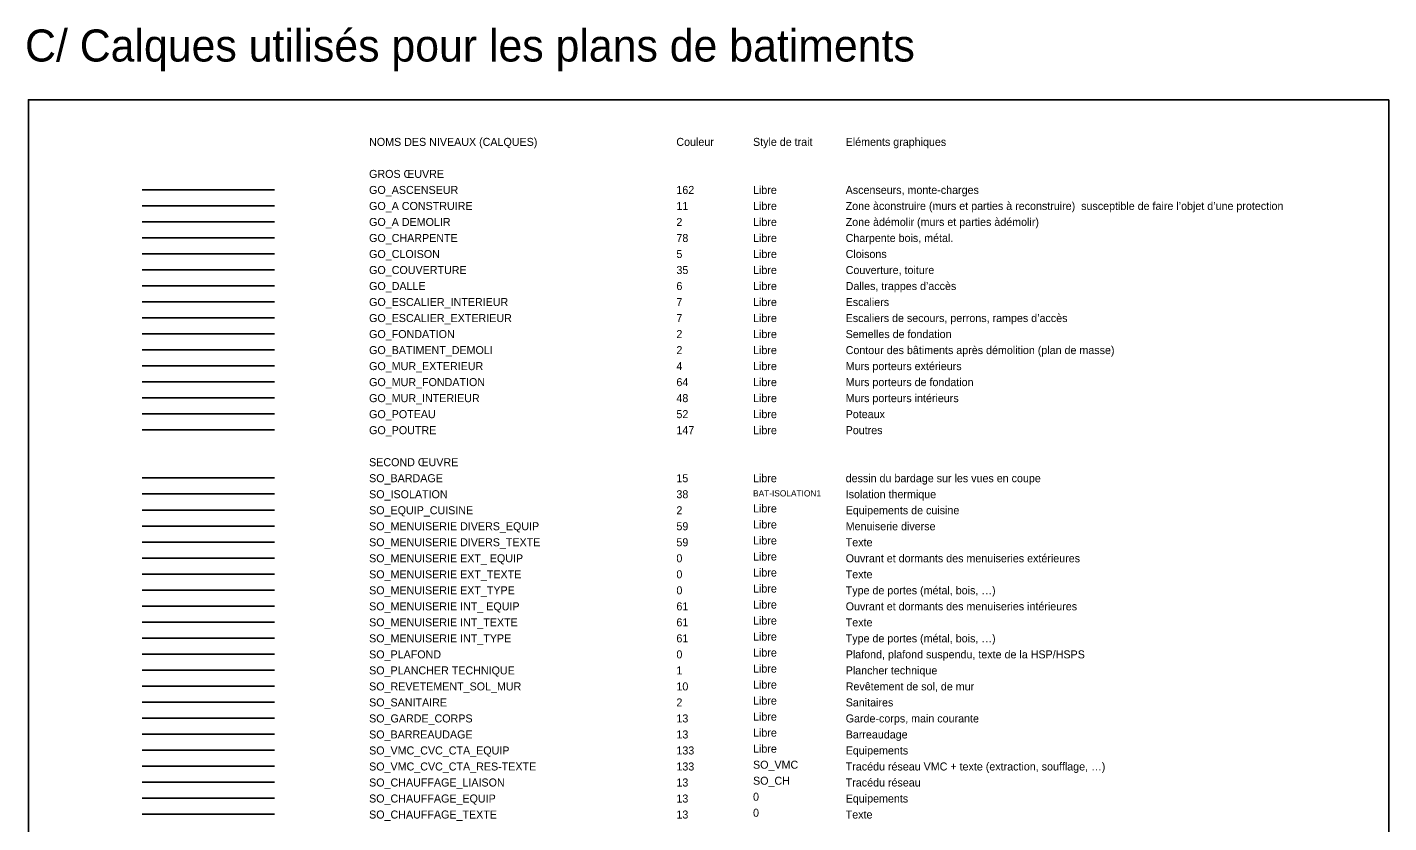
# Model space of a CAD drawing. Extents: x -60 to 214, y -380 to -21.
# Drawn here: x 123.6 to 208.7, y -70.9 to -21.2 of the extents above; entities that cross this region are included whole.
import ezdxf

# ---------------------------------------------------------------- set-up
doc = ezdxf.new("R2010")
doc.units = 0
for name, color, linetype in [('Default', 7, 'Continuous'), ('DH_TEXTE', 7, 'Continuous'), ('GO_A CONSTRUIRE', 7, 'Continuous'), ('GO_A DEMOLIR', 7, 'Continuous'), ('GO_ASCENSEUR', 7, 'Continuous'), ('GO_BATIMENT_DEMOLI', 7, 'Continuous'), ('GO_CHARPENTE', 7, 'Continuous'), ('GO_CLOISON', 7, 'Continuous'), ('GO_COUVERTURE', 7, 'Continuous'), ('GO_DALLE', 7, 'Continuous'), ('GO_ESCALIER_EXTERIEUR', 7, 'Continuous'), ('GO_ESCALIER_INTERIEUR', 7, 'Continuous'), ('GO_FONDATION', 7, 'Continuous'), ('GO_MUR_EXTERIEUR', 7, 'Continuous'), ('GO_MUR_FONDATION', 7, 'Continuous'), ('GO_MUR_INTERIEUR', 7, 'Continuous'), ('GO_POTEAU', 7, 'Continuous'), ('GO_POUTRE', 7, 'Continuous'), ('SO_BARDAGE', 7, 'Continuous'), ('SO_BARREAUDAGE', 7, 'Continuous'), ('SO_CHAUFFAGE_EQUIP', 7, 'Continuous'), ('SO_CHAUFFAGE_LIAISON', 7, 'Continuous'), ('SO_CHAUFFAGE_TEXTE', 7, 'Continuous'), ('SO_EQUIP_CUISINE', 7, 'Continuous'), ('SO_GARDE_CORPS', 7, 'Continuous'), ('SO_ISOLATION', 7, 'Continuous'), ('SO_MENUISERIE DIVERS_EQUIP', 7, 'Continuous'), ('SO_MENUISERIE DIVERS_TEXTE', 7, 'Continuous'), ('SO_MENUISERIE EXT_ EQUIP', 7, 'Continuous'), ('SO_MENUISERIE EXT_TEXTE', 7, 'Continuous'), ('SO_MENUISERIE EXT_TYPE', 7, 'Continuous'), ('SO_MENUISERIE INT_ EQUIP', 7, 'Continuous'), ('SO_MENUISERIE INT_TEXTE', 7, 'Continuous'), ('SO_MENUISERIE INT_TYPE', 7, 'Continuous'), ('SO_PLAFOND', 7, 'Continuous'), ('SO_PLANCHER TECHNIQUE', 7, 'Continuous'), ('SO_REVETEMENT_SOL_MUR', 7, 'Continuous'), ('SO_SANITAIRE', 7, 'Continuous'), ('SO_VMC_CVC_CTA_EQUIP', 7, 'Continuous'), ('SO_VMC_CVC_CTA_RES-TEXTE', 7, 'Continuous')]:
    doc.layers.add(name, color=color, linetype=linetype)

msp = doc.modelspace()

# ---------------------------------------------------------------- linework, layer by layer
at = {"layer": 'Default'}
msp.add_lwpolyline([(208.701, -25.727), (123.7, -25.727), (123.7, -120.902), (208.701, -120.902)], close=True, dxfattribs=at)
at = {"layer": 'GO_A CONSTRUIRE'}
msp.add_line((139.084, -32.345), (130.805, -32.345), dxfattribs=at)
at = {"layer": 'GO_A DEMOLIR'}
msp.add_line((139.084, -33.345), (130.805, -33.345), dxfattribs=at)
at = {"layer": 'GO_ASCENSEUR'}
msp.add_line((139.084, -31.345), (130.805, -31.345), dxfattribs=at)
at = {"layer": 'GO_BATIMENT_DEMOLI'}
msp.add_line((139.084, -41.345), (130.805, -41.345), dxfattribs=at)
at = {"layer": 'GO_CHARPENTE'}
msp.add_line((139.084, -34.345), (130.805, -34.345), dxfattribs=at)
at = {"layer": 'GO_CLOISON'}
msp.add_line((139.084, -35.345), (130.805, -35.345), dxfattribs=at)
at = {"layer": 'GO_COUVERTURE'}
msp.add_line((139.084, -36.345), (130.805, -36.345), dxfattribs=at)
at = {"layer": 'GO_DALLE'}
msp.add_line((139.084, -37.345), (130.805, -37.345), dxfattribs=at)
at = {"layer": 'GO_ESCALIER_EXTERIEUR'}
msp.add_line((139.084, -39.345), (130.805, -39.345), dxfattribs=at)
at = {"layer": 'GO_ESCALIER_INTERIEUR'}
msp.add_line((139.084, -38.345), (130.805, -38.345), dxfattribs=at)
at = {"layer": 'GO_FONDATION'}
msp.add_line((139.084, -40.345), (130.805, -40.345), dxfattribs=at)
at = {"layer": 'GO_MUR_EXTERIEUR'}
msp.add_line((139.084, -42.345), (130.805, -42.345), dxfattribs=at)
at = {"layer": 'GO_MUR_FONDATION'}
msp.add_line((139.084, -43.345), (130.805, -43.345), dxfattribs=at)
at = {"layer": 'GO_MUR_INTERIEUR'}
msp.add_line((139.084, -44.345), (130.805, -44.345), dxfattribs=at)
at = {"layer": 'GO_POTEAU'}
msp.add_line((139.084, -45.345), (130.805, -45.345), dxfattribs=at)
at = {"layer": 'GO_POUTRE'}
msp.add_line((139.084, -46.345), (130.805, -46.345), dxfattribs=at)
at = {"layer": 'SO_BARDAGE'}
msp.add_line((139.084, -49.345), (130.805, -49.345), dxfattribs=at)
at = {"layer": 'SO_BARREAUDAGE'}
msp.add_line((139.084, -65.345), (130.805, -65.345), dxfattribs=at)
at = {"layer": 'SO_CHAUFFAGE_EQUIP'}
msp.add_line((139.084, -69.345), (130.805, -69.345), dxfattribs=at)
at = {"layer": 'SO_CHAUFFAGE_LIAISON'}
msp.add_line((130.805, -68.345), (139.084, -68.345), dxfattribs=at)
at = {"layer": 'SO_CHAUFFAGE_TEXTE'}
msp.add_line((139.084, -70.345), (130.805, -70.345), dxfattribs=at)
at = {"layer": 'SO_EQUIP_CUISINE'}
msp.add_line((139.084, -51.345), (130.805, -51.345), dxfattribs=at)
at = {"layer": 'SO_GARDE_CORPS'}
msp.add_line((139.084, -64.345), (130.805, -64.345), dxfattribs=at)
at = {"layer": 'SO_ISOLATION'}
msp.add_line((139.084, -50.345), (130.805, -50.345), dxfattribs=at)
at = {"layer": 'SO_MENUISERIE DIVERS_EQUIP'}
msp.add_line((139.084, -52.345), (130.805, -52.345), dxfattribs=at)
at = {"layer": 'SO_MENUISERIE DIVERS_TEXTE'}
msp.add_line((139.084, -53.345), (130.805, -53.345), dxfattribs=at)
at = {"layer": 'SO_MENUISERIE EXT_ EQUIP'}
msp.add_line((139.084, -54.345), (130.805, -54.345), dxfattribs=at)
at = {"layer": 'SO_MENUISERIE EXT_TEXTE'}
msp.add_line((139.084, -55.345), (130.805, -55.345), dxfattribs=at)
at = {"layer": 'SO_MENUISERIE EXT_TYPE'}
msp.add_line((139.084, -56.345), (130.805, -56.345), dxfattribs=at)
at = {"layer": 'SO_MENUISERIE INT_ EQUIP'}
msp.add_line((139.084, -57.345), (130.805, -57.345), dxfattribs=at)
at = {"layer": 'SO_MENUISERIE INT_TEXTE'}
msp.add_line((139.084, -58.345), (130.805, -58.345), dxfattribs=at)
at = {"layer": 'SO_MENUISERIE INT_TYPE'}
msp.add_line((139.084, -59.345), (130.805, -59.345), dxfattribs=at)
at = {"layer": 'SO_PLAFOND'}
msp.add_line((139.084, -60.345), (130.805, -60.345), dxfattribs=at)
at = {"layer": 'SO_PLANCHER TECHNIQUE'}
msp.add_line((139.084, -61.345), (130.805, -61.345), dxfattribs=at)
at = {"layer": 'SO_REVETEMENT_SOL_MUR'}
msp.add_line((139.084, -62.345), (130.805, -62.345), dxfattribs=at)
at = {"layer": 'SO_SANITAIRE'}
msp.add_line((139.084, -63.345), (130.805, -63.345), dxfattribs=at)
at = {"layer": 'SO_VMC_CVC_CTA_EQUIP'}
msp.add_line((139.084, -66.345), (130.805, -66.345), dxfattribs=at)
at = {"layer": 'SO_VMC_CVC_CTA_RES-TEXTE'}
msp.add_line((130.805, -67.345), (139.084, -67.345), dxfattribs=at)

# ---------------------------------------------------------------- texts
at = {"layer": 'Default'}
msp.add_text('C/ Calques utilisés pour les plans de batiments', height=2, dxfattribs=at).set_placement((123.489, -23.342))
at = {"layer": 'DH_TEXTE'}
for s, p in [('Eléments graphiques', (174.765, -28.61)), ('NOMS DES NIVEAUX (CALQUES) ', (144.987, -28.61)), ('Couleur ', (164.186, -28.61)), ('Style de trait ', (168.976, -28.61)), ('GROS ŒUVRE ', (144.987, -30.61)), ('SECOND ŒUVRE ', (144.987, -48.61))]:
    msp.add_text(s, height=0.5, dxfattribs=at).set_placement(p)
at = {"layer": 'GO_A CONSTRUIRE'}
for s, p in [('GO_A CONSTRUIRE  ', (144.987, -32.61)), ('11 ', (164.189, -32.61)), ('Libre ', (168.981, -32.61)), ('Zone àconstruire (murs et parties à reconstruire)  susceptible de faire l’objet d’une protection ', (174.765, -32.61))]:
    msp.add_text(s, height=0.5, dxfattribs=at).set_placement(p)
at = {"layer": 'GO_A DEMOLIR'}
for s, p in [('GO_A DEMOLIR  ', (144.987, -33.61)), ('2 ', (164.189, -33.61)), ('Libre ', (168.981, -33.61)), ('Zone àdémolir (murs et parties àdémolir) ', (174.765, -33.61))]:
    msp.add_text(s, height=0.5, dxfattribs=at).set_placement(p)
at = {"layer": 'GO_ASCENSEUR'}
for s, p in [('GO_ASCENSEUR ', (144.987, -31.61)), ('162 ', (164.186, -31.61)), ('Libre ', (168.976, -31.61)), ('Ascenseurs, monte-charges  ', (174.765, -31.61))]:
    msp.add_text(s, height=0.5, dxfattribs=at).set_placement(p)
at = {"layer": 'GO_BATIMENT_DEMOLI'}
for s, p in [('GO_BATIMENT_DEMOLI ', (144.987, -41.61)), ('2 ', (164.189, -41.61)), ('Libre ', (168.981, -41.61)), ('Contour des bâtiments après démolition (plan de masse) ', (174.765, -41.61))]:
    msp.add_text(s, height=0.5, dxfattribs=at).set_placement(p)
at = {"layer": 'GO_CHARPENTE'}
for s, p in [('GO_CHARPENTE ', (144.987, -34.61)), ('78 ', (164.189, -34.61)), ('Libre ', (168.981, -34.61)), ('Charpente bois, métal. ', (174.765, -34.61))]:
    msp.add_text(s, height=0.5, dxfattribs=at).set_placement(p)
at = {"layer": 'GO_CLOISON'}
for s, p in [('GO_CLOISON ', (144.987, -35.61)), ('5 ', (164.189, -35.61)), ('Libre ', (168.981, -35.61)), ('Cloisons  ', (174.765, -35.61))]:
    msp.add_text(s, height=0.5, dxfattribs=at).set_placement(p)
at = {"layer": 'GO_COUVERTURE'}
for s, p in [('GO_COUVERTURE ', (144.987, -36.61)), ('35 ', (164.189, -36.61)), ('Libre ', (168.981, -36.61)), ('Couverture, toiture ', (174.765, -36.61))]:
    msp.add_text(s, height=0.5, dxfattribs=at).set_placement(p)
at = {"layer": 'GO_DALLE'}
for s, p in [('GO_DALLE ', (144.987, -37.61)), ('6 ', (164.189, -37.61)), ('Libre ', (168.981, -37.61)), ('Dalles, trappes d’accès ', (174.765, -37.61))]:
    msp.add_text(s, height=0.5, dxfattribs=at).set_placement(p)
at = {"layer": 'GO_ESCALIER_EXTERIEUR'}
for s, p in [('GO_ESCALIER_EXTERIEUR ', (144.987, -39.61)), ('7 ', (164.189, -39.61)), ('Libre ', (168.981, -39.61)), ('Escaliers de secours, perrons, rampes d’accès ', (174.765, -39.61))]:
    msp.add_text(s, height=0.5, dxfattribs=at).set_placement(p)
at = {"layer": 'GO_ESCALIER_INTERIEUR'}
for s, p in [('GO_ESCALIER_INTERIEUR ', (144.987, -38.61)), ('7 ', (164.189, -38.61)), ('Libre ', (168.981, -38.61)), ('Escaliers ', (174.765, -38.61))]:
    msp.add_text(s, height=0.5, dxfattribs=at).set_placement(p)
at = {"layer": 'GO_FONDATION'}
for s, p in [('GO_FONDATION ', (144.987, -40.61)), ('2 ', (164.189, -40.61)), ('Libre ', (168.981, -40.61)), ('Semelles de fondation ', (174.765, -40.61))]:
    msp.add_text(s, height=0.5, dxfattribs=at).set_placement(p)
at = {"layer": 'GO_MUR_EXTERIEUR'}
for s, p in [('GO_MUR_EXTERIEUR          ', (144.987, -42.61)), ('4 ', (164.189, -42.61)), ('Libre ', (168.981, -42.61)), ('Murs porteurs extérieurs  ', (174.765, -42.61))]:
    msp.add_text(s, height=0.5, dxfattribs=at).set_placement(p)
at = {"layer": 'GO_MUR_FONDATION'}
for s, p in [('GO_MUR_FONDATION ', (144.987, -43.61)), ('64 ', (164.189, -43.61)), ('Libre ', (168.981, -43.61)), ('Murs porteurs de fondation  ', (174.765, -43.61))]:
    msp.add_text(s, height=0.5, dxfattribs=at).set_placement(p)
at = {"layer": 'GO_MUR_INTERIEUR'}
for s, p in [('GO_MUR_INTERIEUR                ', (144.987, -44.61)), ('48 ', (164.189, -44.61)), ('Libre ', (168.981, -44.61)), ('Murs porteurs intérieurs  ', (174.765, -44.61))]:
    msp.add_text(s, height=0.5, dxfattribs=at).set_placement(p)
at = {"layer": 'GO_POTEAU'}
for s, p in [('Libre ', (168.981, -45.61)), ('GO_POTEAU ', (144.987, -45.61)), ('52 ', (164.189, -45.61)), ('Poteaux  ', (174.765, -45.61))]:
    msp.add_text(s, height=0.5, dxfattribs=at).set_placement(p)
at = {"layer": 'GO_POUTRE'}
for s, p in [('GO_POUTRE ', (144.987, -46.61)), ('147 ', (164.189, -46.61)), ('Libre ', (168.981, -46.61)), ('Poutres  ', (174.765, -46.61))]:
    msp.add_text(s, height=0.5, dxfattribs=at).set_placement(p)
at = {"layer": 'SO_BARDAGE'}
for s, p in [('SO_BARDAGE ', (144.987, -49.61)), ('15 ', (164.186, -49.61)), ('Libre ', (168.976, -49.61)), ('dessin du bardage sur les vues en coupe ', (174.765, -49.61))]:
    msp.add_text(s, height=0.5, dxfattribs=at).set_placement(p)
at = {"layer": 'SO_BARREAUDAGE'}
for s, p in [('SO_BARREAUDAGE ', (144.987, -65.61)), ('13 ', (164.189, -65.61)), ('Libre ', (168.978, -65.499)), ('Barreaudage ', (174.768, -65.61))]:
    msp.add_text(s, height=0.5, dxfattribs=at).set_placement(p)
at = {"layer": 'SO_CHAUFFAGE_EQUIP'}
for s, p in [('SO_CHAUFFAGE_EQUIP ', (144.987, -69.61)), ('13 ', (164.189, -69.61)), ('0 ', (168.978, -69.499)), ('Equipements ', (174.768, -69.61))]:
    msp.add_text(s, height=0.5, dxfattribs=at).set_placement(p)
at = {"layer": 'SO_CHAUFFAGE_LIAISON'}
for s, p in [('SO_CH ', (168.978, -68.499)), ('SO_CHAUFFAGE_LIAISON ', (144.987, -68.61)), ('13 ', (164.189, -68.61)), ('Tracédu réseau ', (174.768, -68.61))]:
    msp.add_text(s, height=0.5, dxfattribs=at).set_placement(p)
at = {"layer": 'SO_CHAUFFAGE_TEXTE'}
for s, p in [('SO_CHAUFFAGE_TEXTE ', (144.987, -70.61)), ('13 ', (164.189, -70.61)), ('0 ', (168.978, -70.499)), ('Texte ', (174.768, -70.61))]:
    msp.add_text(s, height=0.5, dxfattribs=at).set_placement(p)
at = {"layer": 'SO_EQUIP_CUISINE'}
for s, p in [('Libre ', (168.978, -51.499)), ('SO_EQUIP_CUISINE ', (144.987, -51.61)), ('2 ', (164.189, -51.61)), ('Equipements de cuisine ', (174.768, -51.61))]:
    msp.add_text(s, height=0.5, dxfattribs=at).set_placement(p)
at = {"layer": 'SO_GARDE_CORPS'}
for s, p in [('SO_GARDE_CORPS ', (144.987, -64.61)), ('13 ', (164.189, -64.61)), ('Libre ', (168.978, -64.499)), ('Garde-corps, main courante  ', (174.768, -64.61))]:
    msp.add_text(s, height=0.5, dxfattribs=at).set_placement(p)
at = {"layer": 'SO_ISOLATION'}
for s, height, p in [('SO_ISOLATION  ', 0.5, (144.987, -50.61)), ('38 ', 0.5, (164.189, -50.61)), ('BAT-ISOLATION1 ', 0.38889, (168.978, -50.499)), ('Isolation thermique ', 0.5, (174.768, -50.61))]:
    msp.add_text(s, height=height, dxfattribs=at).set_placement(p)
at = {"layer": 'SO_MENUISERIE DIVERS_EQUIP'}
for s, p in [('SO_MENUISERIE DIVERS_EQUIP ', (144.987, -52.61)), ('59 ', (164.189, -52.61)), ('Libre ', (168.978, -52.499)), ('Menuiserie diverse ', (174.768, -52.61))]:
    msp.add_text(s, height=0.5, dxfattribs=at).set_placement(p)
at = {"layer": 'SO_MENUISERIE DIVERS_TEXTE'}
for s, p in [('SO_MENUISERIE DIVERS_TEXTE  ', (144.987, -53.61)), ('59 ', (164.189, -53.61)), ('Libre ', (168.978, -53.499)), ('Texte  ', (174.768, -53.61))]:
    msp.add_text(s, height=0.5, dxfattribs=at).set_placement(p)
at = {"layer": 'SO_MENUISERIE EXT_ EQUIP'}
for s, p in [('SO_MENUISERIE EXT_ EQUIP ', (144.987, -54.61)), ('0 ', (164.189, -54.61)), ('Libre ', (168.978, -54.499)), ('Ouvrant et dormants des menuiseries extérieures ', (174.768, -54.61))]:
    msp.add_text(s, height=0.5, dxfattribs=at).set_placement(p)
at = {"layer": 'SO_MENUISERIE EXT_TEXTE'}
for s, p in [('SO_MENUISERIE EXT_TEXTE ', (144.987, -55.61)), ('0 ', (164.189, -55.61)), ('Libre ', (168.978, -55.499)), ('Texte  ', (174.768, -55.61))]:
    msp.add_text(s, height=0.5, dxfattribs=at).set_placement(p)
at = {"layer": 'SO_MENUISERIE EXT_TYPE'}
for s, p in [('SO_MENUISERIE EXT_TYPE ', (144.987, -56.61)), ('0 ', (164.189, -56.61)), ('Libre ', (168.978, -56.499)), ('Type de portes (métal, bois, …) ', (174.768, -56.61))]:
    msp.add_text(s, height=0.5, dxfattribs=at).set_placement(p)
at = {"layer": 'SO_MENUISERIE INT_ EQUIP'}
for s, p in [('Libre ', (168.978, -57.499)), ('SO_MENUISERIE INT_ EQUIP ', (144.987, -57.61)), ('61 ', (164.189, -57.61)), ('Ouvrant et dormants des menuiseries intérieures ', (174.768, -57.61))]:
    msp.add_text(s, height=0.5, dxfattribs=at).set_placement(p)
at = {"layer": 'SO_MENUISERIE INT_TEXTE'}
for s, p in [('SO_MENUISERIE INT_TEXTE ', (144.987, -58.61)), ('61 ', (164.189, -58.61)), ('Libre ', (168.978, -58.499)), ('Texte ', (174.768, -58.61))]:
    msp.add_text(s, height=0.5, dxfattribs=at).set_placement(p)
at = {"layer": 'SO_MENUISERIE INT_TYPE'}
for s, p in [('SO_MENUISERIE INT_TYPE ', (144.987, -59.61)), ('61 ', (164.189, -59.61)), ('Libre ', (168.978, -59.499)), ('Type de portes (métal, bois, …) ', (174.768, -59.61))]:
    msp.add_text(s, height=0.5, dxfattribs=at).set_placement(p)
at = {"layer": 'SO_PLAFOND'}
for s, p in [('SO_PLAFOND  ', (144.987, -60.61)), ('0 ', (164.189, -60.61)), ('Libre ', (168.978, -60.499)), ('Plafond, plafond suspendu, texte de la HSP/HSPS ', (174.768, -60.61))]:
    msp.add_text(s, height=0.5, dxfattribs=at).set_placement(p)
at = {"layer": 'SO_PLANCHER TECHNIQUE'}
for s, p in [('SO_PLANCHER TECHNIQUE  ', (144.987, -61.61)), ('1 ', (164.189, -61.61)), ('Libre ', (168.978, -61.499)), ('Plancher technique  ', (174.768, -61.61))]:
    msp.add_text(s, height=0.5, dxfattribs=at).set_placement(p)
at = {"layer": 'SO_REVETEMENT_SOL_MUR'}
for s, p in [('SO_REVETEMENT_SOL_MUR  ', (144.987, -62.61)), ('10 ', (164.189, -62.61)), ('Libre ', (168.978, -62.499)), ('Revêtement de sol, de mur  ', (174.768, -62.61))]:
    msp.add_text(s, height=0.5, dxfattribs=at).set_placement(p)
at = {"layer": 'SO_SANITAIRE'}
for s, p in [('SO_SANITAIRE ', (144.987, -63.61)), ('2 ', (164.189, -63.61)), ('Libre ', (168.978, -63.499)), ('Sanitaires  ', (174.768, -63.61))]:
    msp.add_text(s, height=0.5, dxfattribs=at).set_placement(p)
at = {"layer": 'SO_VMC_CVC_CTA_EQUIP'}
for s, p in [('SO_VMC_CVC_CTA_EQUIP ', (144.987, -66.61)), ('133 ', (164.189, -66.61)), ('Libre ', (168.978, -66.499)), ('Equipements ', (174.768, -66.61))]:
    msp.add_text(s, height=0.5, dxfattribs=at).set_placement(p)
at = {"layer": 'SO_VMC_CVC_CTA_RES-TEXTE'}
for s, p in [('SO_VMC_CVC_CTA_RES-TEXTE ', (144.987, -67.61)), ('133 ', (164.189, -67.61)), ('SO_VMC ', (168.978, -67.499)), ('Tracédu réseau VMC + texte (extraction, soufflage, …) ', (174.768, -67.61))]:
    msp.add_text(s, height=0.5, dxfattribs=at).set_placement(p)

doc.saveas('drawing.dxf')
